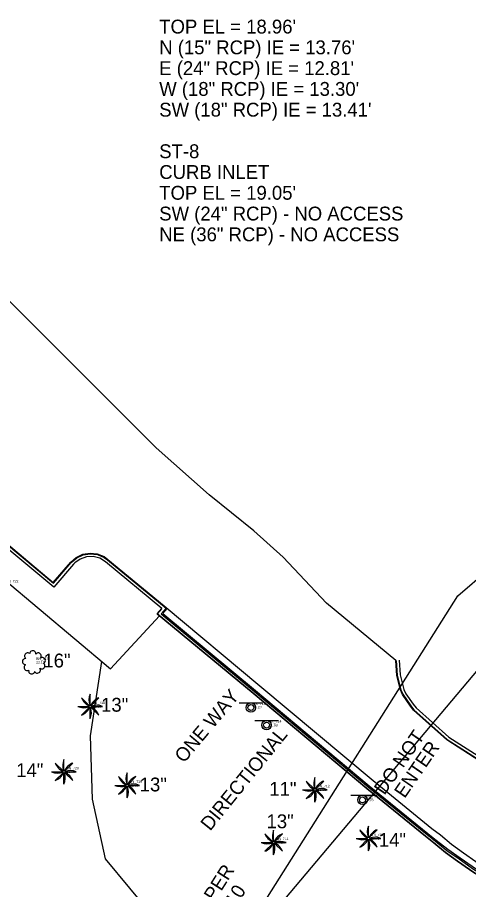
# Model space of a CAD drawing. Extents: x 509744 to 512285, y 1314862 to 1316822.
# Drawn here: x 510638.5 to 510729.8, y 1315574.9 to 1315751.2 of the extents above; entities that cross this region are included whole.
import ezdxf

# ---------------------------------------------------------------- set-up
doc = ezdxf.new("R2010")
doc.units = 0
for name, color, linetype in [('CGBack_ep', 7, 'Continuous'), ('CGep_ep', 7, 'Continuous'), ('CGFace_ep', 7, 'Continuous'), ('Driveway_ep', 7, 'Continuous'), ('ElecAer_ep', 7, 'Continuous'), ('LandscapeBordr_ep', 7, 'Continuous'), ('LARWLine_ep', 7, 'Continuous'), ('NonPlottingEle_dp', 7, 'Continuous'), ('PavtMisc_ep', 7, 'Continuous'), ('SidewalkBack_ep', 7, 'Continuous'), ('SignSingle_ep', 7, 'Continuous'), ('TextElevLabel', 7, 'Continuous'), ('TextNotes', 7, 'Continuous'), ('TextPtLabel', 7, 'Continuous'), ('TextTopoLabel_ep', 7, 'Continuous'), ('TreeOak_ep', 7, 'Continuous'), ('TreePalm_ep', 7, 'Continuous')]:
    doc.layers.add(name, color=color, linetype=linetype)

msp = doc.modelspace()

# ---------------------------------------------------------------- linework, layer by layer
at = {"layer": 'CGBack_ep'}
for p, q in [((510649.88, 1315640.69), (510645.86, 1315636.01)), ((510667.7, 1315631.73), (510656.33, 1315641.17)), ((510666.79, 1315630.63), (510667.7, 1315631.73)), ((510667.7, 1315631.73), (510666.79, 1315630.63)), ((510667.7, 1315631.73), (510667.7, 1315631.73))]:
    msp.add_line(p, q, dxfattribs=at)
for points in [[(510645.86, 1315636.01), (510625.95, 1315652.64), (510598.17, 1315675.6), (510570.45, 1315698.57), (510541.41, 1315722.58)], [(510656.33, 1315641.17), (510655.16, 1315641.88), (510653.84, 1315642.22), (510652.48, 1315642.16), (510651.2, 1315641.72), (510650.1, 1315640.92), (510649.88, 1315640.69)], [(510737.41, 1315575.2), (510733.49, 1315576.82), (510730.86, 1315578.34), (510729.97, 1315578.94), (510727.51, 1315580.64), (510725.08, 1315582.41), (510722.77, 1315584.35), (510721.08, 1315585.67), (510709.18, 1315595.32), (510686.17, 1315614.58), (510666.79, 1315630.63)], [(510666.79, 1315630.63), (510686.17, 1315614.58), (510709.18, 1315595.32), (510721.08, 1315585.67), (510722.77, 1315584.35), (510725.08, 1315582.41), (510727.51, 1315580.64), (510729.97, 1315578.94), (510730.86, 1315578.34), (510733.49, 1315576.82), (510737.41, 1315575.2)], [(510715.72, 1315621.3), (510715.92, 1315618.29), (510716.67, 1315615.37), (510717.09, 1315614.48), (510718.55, 1315612.41), (510719.18, 1315611.63), (510725.8, 1315605.69), (510732.42, 1315601.49)]]:
    msp.add_lwpolyline(points, dxfattribs=at)
at = {"layer": 'CGep_ep'}
msp.add_line((510667.94, 1315630.71), (510668.81, 1315631.73), dxfattribs=at)
msp.add_lwpolyline([(510667.94, 1315630.71), (510686.68, 1315615.13), (510709.65, 1315595.9), (510721.53, 1315586.23), (510723.21, 1315584.89), (510725.56, 1315583.06), (510728.03, 1315581.34), (510730.49, 1315579.63), (510731.38, 1315579.03), (510733.92, 1315577.57), (510737.54, 1315575.61)], dxfattribs=at)
at = {"layer": 'CGFace_ep'}
for p, q in [((510645.78, 1315636.83), (510649.4, 1315641.03)), ((510656.74, 1315641.57), (510668.57, 1315631.77)), ((510667.61, 1315630.66), (510668.57, 1315631.77))]:
    msp.add_line(p, q, dxfattribs=at)
for points in [[(510542.23, 1315722.66), (510570.82, 1315699.02), (510598.54, 1315676.05), (510626.32, 1315653.09), (510645.78, 1315636.83)], [(510649.4, 1315641.03), (510650.5, 1315641.97), (510651.83, 1315642.57), (510653.26, 1315642.8), (510654.71, 1315642.62), (510656.05, 1315642.06), (510656.74, 1315641.57)], [(510667.61, 1315630.66), (510686.5, 1315614.93), (510709.48, 1315595.7), (510721.36, 1315586.02), (510723.05, 1315584.7), (510725.37, 1315582.8), (510727.83, 1315581.08), (510730.3, 1315579.37), (510731.19, 1315578.78), (510733.78, 1315577.31), (510737.52, 1315575.56)], [(510715.14, 1315621.2), (510715.33, 1315618.19), (510716.08, 1315615.27), (510716.5, 1315614.38), (510718.09, 1315612.03), (510718.72, 1315611.25), (510725.41, 1315605.24), (510732.13, 1315600.99)]]:
    msp.add_lwpolyline(points, dxfattribs=at)
at = {"layer": 'Driveway_ep'}
for p, q in [((510645.77, 1315637.01), (510649.29, 1315641.1)), ((510656.83, 1315641.66), (510668.18, 1315632.26))]:
    msp.add_line(p, q, dxfattribs=at)
for points in [[(510542.41, 1315722.68), (510570.9, 1315699.12), (510598.62, 1315676.15), (510626.41, 1315653.19), (510645.77, 1315637.01)], [(510649.29, 1315641.1), (510650.41, 1315642.06), (510651.75, 1315642.68), (510653.2, 1315642.92), (510654.67, 1315642.76), (510656.03, 1315642.21), (510656.83, 1315641.66)], [(510668.18, 1315632.26), (510687.57, 1315616.1), (510710.48, 1315596.92), (510722.36, 1315587.25), (510724.06, 1315585.94), (510726.31, 1315584.05), (510728.75, 1315582.3), (510731.22, 1315580.59), (510732.11, 1315580), (510734.53, 1315578.61), (510737.93, 1315576.83)], [(510732.07, 1315600.88), (510725.35, 1315605.16), (510718.64, 1315611.19), (510718.01, 1315611.97), (510716.4, 1315614.36), (510715.98, 1315615.26), (510715.23, 1315618.17), (510715.03, 1315621.18)]]:
    msp.add_lwpolyline(points, dxfattribs=at)
at = {"layer": 'ElecAer_ep'}
msp.add_lwpolyline([(510673.59, 1315425.92), (510652.87, 1315530.2), (510676.08, 1315553.36), (510865.37, 1315778.14)], dxfattribs=at)
at = {"layer": 'LandscapeBordr_ep'}
msp.add_lwpolyline([(510655.55, 1315621.03), (510653.26, 1315605.97), (510653.62, 1315593.19), (510656.25, 1315581.14), (510671.03, 1315563.35), (510687.42, 1315548.24), (510696.51, 1315531.6)], dxfattribs=at)
at = {"layer": 'LARWLine_ep'}
for p, q in [((510727.56, 1315634.29), (510840.71, 1315731.11)), ((510656.69, 1315522.18), (510727.56, 1315634.29))]:
    msp.add_line(p, q, dxfattribs=at)
at = {"layer": 'PavtMisc_ep'}
msp.add_lwpolyline([(510715.03, 1315621.18), (510701.02, 1315632.77), (510692.29, 1315642.07), (510686.35, 1315647.43), (510677.27, 1315654.69), (510666.59, 1315664.2), (510632.5, 1315698.19), (510628.49, 1315703.22)], dxfattribs=at)
at = {"layer": 'SidewalkBack_ep'}
msp.add_lwpolyline([(510599.58, 1315668.01), (510657.37, 1315619.5), (510667.27, 1315630.24)], dxfattribs=at)
at = {"layer": 'SignSingle_ep'}
for p, q in [((510683.36, 1315612.65), (510688.11, 1315612.65)), ((510686.52, 1315609.1), (510691.27, 1315609.1)), ((510705.93, 1315593.97), (510710.68, 1315593.97))]:
    msp.add_line(p, q, dxfattribs=at)
for centre, radius in [((510685.73, 1315611.7), 0.95), ((510685.73, 1315611.7), 0.594), ((510688.9, 1315608.15), 0.95), ((510688.9, 1315608.15), 0.594), ((510708.3, 1315593.02), 0.95), ((510708.3, 1315593.02), 0.594)]:
    msp.add_circle(centre, radius, dxfattribs=at)
at = {"layer": 'TreeOak_ep'}
for centre, radius, start, end in [((510640.58, 1315622.11), 0.624, 50.7185, 233.084), ((510641.6, 1315622.55), 0.629, 355.3943, 176.6549), ((510642.71, 1315622.11), 0.627, 315.0898, 140.6833), ((510640.17, 1315620.98), 0.625, 87.3095, 269.5618), ((510643.54, 1315621.17), 0.626, 299.4354, 127.2613), ((510640.48, 1315619.81), 0.626, 119.4469, 301.0197), ((510641.4, 1315619.11), 0.625, 164.2871, 346.2767), ((510642.54, 1315619.29), 0.628, 211.1877, 36.8199), ((510643.45, 1315620.13), 0.623, 229.2872, 51.2025)]:
    msp.add_arc(centre, radius, start, end, dxfattribs=at)
at = {"layer": 'TreePalm_ep'}
for p, q in [((510653.22, 1315612.17), (510653.22, 1315614.42)), ((510653.05, 1315612.09), (510651.46, 1315613.68)), ((510653.4, 1315612.09), (510654.99, 1315613.68)), ((510650.72, 1315611.92), (510652.97, 1315611.92)), ((510651.46, 1315610.15), (510653.05, 1315611.74)), ((510653.22, 1315609.42), (510653.22, 1315611.67)), ((510654.99, 1315610.15), (510653.4, 1315611.74)), ((510653.47, 1315611.92), (510655.72, 1315611.92)), ((510647.76, 1315598.88), (510646.17, 1315600.47)), ((510647.93, 1315598.95), (510647.93, 1315601.2)), ((510648.11, 1315598.88), (510649.7, 1315600.47)), ((510645.43, 1315598.7), (510647.68, 1315598.7)), ((510646.17, 1315596.94), (510647.76, 1315598.53)), ((510647.93, 1315596.2), (510647.93, 1315598.45)), ((510649.7, 1315596.94), (510648.11, 1315598.53)), ((510648.18, 1315598.7), (510650.43, 1315598.7)), ((510660.71, 1315596.22), (510660.71, 1315598.47)), ((510660.53, 1315596.15), (510658.94, 1315597.74)), ((510660.89, 1315596.15), (510662.48, 1315597.74)), ((510698.52, 1315595.25), (510696.93, 1315596.84)), ((510698.69, 1315595.32), (510698.69, 1315597.57)), ((510698.87, 1315595.25), (510700.46, 1315596.84)), ((510658.21, 1315595.97), (510660.46, 1315595.97)), ((510658.94, 1315594.21), (510660.53, 1315595.8)), ((510660.71, 1315593.47), (510660.71, 1315595.72)), ((510662.48, 1315594.21), (510660.89, 1315595.8)), ((510660.96, 1315595.97), (510663.21, 1315595.97)), ((510696.19, 1315595.07), (510698.44, 1315595.07)), ((510696.93, 1315593.31), (510698.52, 1315594.9)), ((510698.69, 1315592.57), (510698.69, 1315594.82)), ((510700.46, 1315593.31), (510698.87, 1315594.9)), ((510698.94, 1315595.07), (510701.19, 1315595.07)), ((510709.52, 1315585.48), (510709.52, 1315587.73)), ((510690.17, 1315584.58), (510688.58, 1315586.17)), ((510690.34, 1315584.65), (510690.34, 1315586.9)), ((510690.52, 1315584.58), (510692.11, 1315586.17)), ((510709.34, 1315585.41), (510707.75, 1315587)), ((510709.69, 1315585.41), (510711.28, 1315587)), ((510687.84, 1315584.4), (510690.09, 1315584.4)), ((510688.58, 1315582.64), (510690.17, 1315584.23)), ((510690.34, 1315581.9), (510690.34, 1315584.15)), ((510692.11, 1315582.64), (510690.52, 1315584.23)), ((510690.59, 1315584.4), (510692.84, 1315584.4)), ((510707.02, 1315585.23), (510709.27, 1315585.23)), ((510707.75, 1315583.47), (510709.34, 1315585.06)), ((510709.52, 1315582.73), (510709.52, 1315584.98)), ((510711.28, 1315583.47), (510709.69, 1315585.06)), ((510709.77, 1315585.23), (510712.02, 1315585.23))]:
    msp.add_line(p, q, dxfattribs=at)
for centre in [(510653.22, 1315611.92), (510647.93, 1315598.7), (510660.71, 1315595.97), (510698.69, 1315595.07), (510690.34, 1315584.4), (510709.52, 1315585.23)]:
    msp.add_circle(centre, 0.25, dxfattribs=at)
for centre, start, end in [((510656.22, 1315613.17), 157.3801, 198.2114), ((510654.46, 1315614.92), 202.3801, 243.2114), ((510656.23, 1315610.68), 112.3801, 153.2114), ((510654.47, 1315608.92), 67.3801, 108.2114), ((510651.97, 1315614.92), 247.3801, 288.2114), ((510650.22, 1315613.15), 292.3801, 333.2114), ((510650.22, 1315610.67), 337.3801, 18.2114), ((510651.99, 1315608.91), 22.3801, 63.2114), ((510649.17, 1315601.71), 202.3801, 243.2114), ((510650.93, 1315599.95), 157.3801, 198.2114), ((510650.94, 1315597.47), 112.3801, 153.2114), ((510646.68, 1315601.7), 247.3801, 288.2114), ((510644.93, 1315599.94), 292.3801, 333.2114), ((510644.93, 1315597.45), 337.3801, 18.2114), ((510646.7, 1315595.7), 22.3801, 63.2114), ((510649.18, 1315595.7), 67.3801, 108.2114), ((510663.71, 1315597.22), 157.3801, 198.2114), ((510661.95, 1315598.98), 202.3801, 243.2114), ((510663.72, 1315594.74), 112.3801, 153.2114), ((510699.93, 1315598.08), 202.3801, 243.2114), ((510701.69, 1315596.32), 157.3801, 198.2114), ((510701.7, 1315593.84), 112.3801, 153.2114), ((510659.46, 1315598.97), 247.3801, 288.2114), ((510657.71, 1315597.21), 292.3801, 333.2114), ((510657.71, 1315594.72), 337.3801, 18.2114), ((510659.47, 1315592.97), 22.3801, 63.2114), ((510661.96, 1315592.97), 67.3801, 108.2114), ((510697.44, 1315598.07), 247.3801, 288.2114), ((510695.69, 1315596.31), 292.3801, 333.2114), ((510695.69, 1315593.82), 337.3801, 18.2114), ((510697.46, 1315592.07), 22.3801, 63.2114), ((510699.94, 1315592.07), 67.3801, 108.2114), ((510712.52, 1315586.48), 157.3801, 198.2114), ((510691.58, 1315587.41), 202.3801, 243.2114), ((510693.34, 1315585.65), 157.3801, 198.2114), ((510693.35, 1315583.17), 112.3801, 153.2114), ((510710.75, 1315588.24), 202.3801, 243.2114), ((510712.52, 1315584), 112.3801, 153.2114), ((510689.09, 1315587.4), 247.3801, 288.2114), ((510687.34, 1315585.64), 292.3801, 333.2114), ((510687.34, 1315583.15), 337.3801, 18.2114), ((510689.11, 1315581.4), 22.3801, 63.2114), ((510691.59, 1315581.4), 67.3801, 108.2114), ((510708.27, 1315588.23), 247.3801, 288.2114), ((510706.51, 1315586.47), 292.3801, 333.2114), ((510706.52, 1315583.98), 337.3801, 18.2114), ((510708.28, 1315582.23), 22.3801, 63.2114), ((510710.77, 1315582.23), 67.3801, 108.2114)]:
    msp.add_arc(centre, 3.25, start, end, dxfattribs=at)

# ---------------------------------------------------------------- texts
at = {"layer": 'NonPlottingEle_dp'}
for s, p in [("TOP EL = 18.96'", (510667.2, 1315747.96)), ('N (15" RCP) IE = 13.76\'', (510667.2, 1315743.76)), ('E (24" RCP) IE = 12.81\'', (510667.2, 1315739.56)), ('W (18" RCP) IE = 13.30\'', (510667.2, 1315735.36)), ('SW (18" RCP) IE = 13.41\'', (510667.2, 1315731.16)), ('ST-8', (510667.2, 1315722.76)), ('CURB INLET', (510667.2, 1315718.56)), ("TOP EL = 19.05'", (510667.2, 1315714.36)), ('SW (24" RCP) - NO ACCESS', (510667.2, 1315710.16)), ('NE (36" RCP) - NO ACCESS', (510667.2, 1315705.96))]:
    msp.add_text(s, height=2.8, dxfattribs=at).set_placement(p)
at = {"layer": 'TextElevLabel'}
for s, p in [('22.18', (510642.31, 1315620.58)), ('21.88', (510653.72, 1315611.67)), ('21.02', (510686.23, 1315611.45)), ('21.08', (510689.4, 1315607.9)), ('22.06', (510648.43, 1315598.45)), ('21.83', (510661.21, 1315595.72)), ('21.06', (510699.19, 1315594.82)), ('20.76', (510708.8, 1315592.77)), ('21.38', (510690.84, 1315584.15)), ('20.76', (510710.02, 1315584.98))]:
    msp.add_text(s, height=0.5, dxfattribs=at).set_placement(p)
at = {"layer": 'TextNotes'}
for s, p in [('EXISTING L.A. R/W LINE PER', (510654.88, 1315535.26)), ('THEA SEC. 10002-2520-010', (510659, 1315533.92))]:
    msp.add_text(s, height=2.8, rotation=57.615, dxfattribs=at).set_placement(p)
at = {"layer": 'TextPtLabel'}
for s, p in [('BN_722', (510636.22, 1315637)), ('BN_717', (510642.31, 1315621.33)), ('BN_718', (510653.72, 1315612.42)), ('BN_715', (510686.23, 1315612.2)), ('BN_714', (510689.4, 1315608.65)), ('BN_720', (510648.43, 1315599.2)), ('BN_719', (510661.21, 1315596.47)), ('BN_712', (510699.19, 1315595.57)), ('BN_713', (510708.8, 1315593.52)), ('BN_710', (510710.02, 1315585.73)), ('BN_711', (510690.84, 1315584.9))]:
    msp.add_text(s, height=0.5, dxfattribs=at).set_placement(p)
at = {"layer": 'TextTopoLabel_ep'}
for s, p in [('16"', (510643.77, 1315619.8)), ('13"', (510655.44, 1315610.86)), ('14"', (510638.27, 1315597.64)), ('13"', (510663.25, 1315594.74)), ('11"', (510689.46, 1315593.86)), ('13"', (510688.9, 1315587.3)), ('14"', (510711.61, 1315583.56))]:
    msp.add_text(s, height=2.8, dxfattribs=at).set_placement(p)
for s, rotation, p in [('ONE WAY', 50.0549, (510672.19, 1315600.33)), ('DO NOT', 55.498, (510712.74, 1315593.85)), ('DIRECTIONAL', 51.0693, (510677.49, 1315586.6)), ('ENTER', 55.498, (510716.83, 1315593.2))]:
    msp.add_text(s, height=2.8, rotation=rotation, dxfattribs=at).set_placement(p)

doc.saveas('drawing.dxf')
